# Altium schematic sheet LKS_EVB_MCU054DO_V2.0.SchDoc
size A4; SheetNumber: 1; SheetTotal: 1
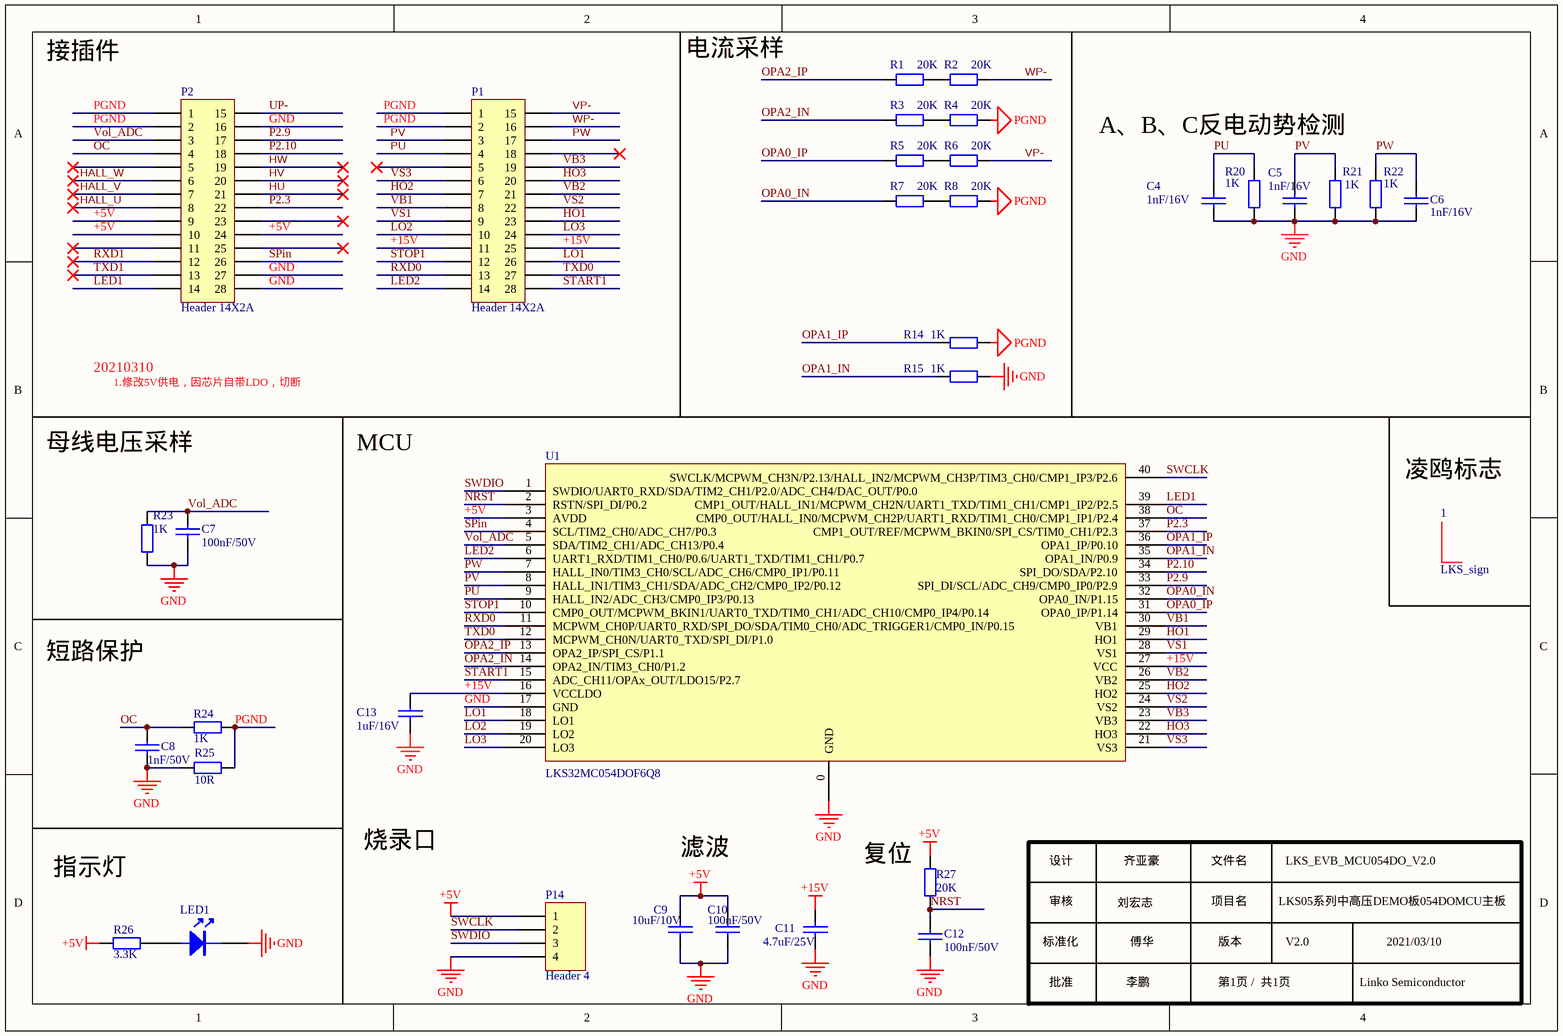
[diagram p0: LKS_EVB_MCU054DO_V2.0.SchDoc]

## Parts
1  LKS_sign  [LKS_LOGO2]
C4  1nF/16V  [0603C]
C5  1nF/16V  [0603C]
C6  1nF/16V  [0603C]
C7  100nF/50V  [0603C]
C8  1nF/50V  [0603C]
C9  10uF/10V  [0603C]
C10  100nF/50V  [0603C]
C11  4.7uF/25V  [0603C]
C12  100nF/50V  [0603C]
C13  1uF/16V  [0603C]
LED1  LED  [LED 0603R]  (value not drawn)
P1  Header 14X2A  [HDR2X14_CEN]
P2  Header 14X2A  [HDR2X14_CEN]
P14  Header 4  [HDR1X4]
R1  20K  [0603R]
R2  20K  [0603R]
R3  20K  [0603R]
R4  20K  [0603R]
R5  20K  [0603R]
R6  20K  [0603R]
R7  20K  [0603R]
R8  20K  [0603R]
R14  1K  [0603R]
R15  1K  [0603R]
R20  1K  [0603R]
R21  1K  [0603R]
R22  1K  [0603R]
R23  1K  [0603R]
R24  1K  [0603R]
R25  10R  [0603R]
R26  3.3K  [0603R]
R27  20K  [0603R]
U1  LKS32MC054DOF6Q8  [QFN40]

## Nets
+5V: C9.2 C10.2 P2.9 P2.10 P2.24 P14.1 R26.2 R27.1 U1.3(AVDD)
+15V: C11.2 C13.1 P1.11 P1.25 U1.16(VCCLDO) U1.27(VCC)
GND: C4.2 C5.2 C6.2 C7.1 C8.1 C9.1 C10.1 C11.1 C12.2 C13.2 LED1.2(K) P2.16 P2.27 P2.28 P14.4 R15.1 R20.2 R21.2 R22.2 R23.1 R25.2 U1.0(GND) U1.17(GND)
PGND: P1.1 P1.2 P2.1 P2.2 R4.1 R8.1 R14.1 R24.2 R25.1
HALL_U: P2.8
HALL_V: P2.7
HALL_W: P2.6
HO1: P1.23 U1.29(HO1)
HO2: P1.7 U1.25(HO2)
HO3: P1.20 U1.22(HO3)
HU: P2.21
HV: P2.20
HW: P2.19
LED1: P2.14 U1.39(CMP1_OUT/HALL_IN1/MCPWM_CH2N/UART1_TXD/TIM1_CH1/CMP1_IP2/P2.5)
LED2: P1.14 U1.6(UART1_RXD/TIM1_CH0/P0.6/UART1_TXD/TIM1_CH1/P0.7)
LO1: P1.26 U1.18(LO1)
LO2: P1.10 U1.19(LO2)
LO3: P1.24 U1.20(LO3)
NRST: C12.1 R27.2 U1.2(RSTN/SPI_DI/P0.2)
OC: C8.2 P2.4 R24.1 U1.38(CMP0_OUT/HALL_IN0/MCPWM_CH2P/UART1_RXD/TIM1_CH0/CMP1_IP1/P2.4)
OPA0_IN: R7.2 U1.32(OPA0_IN/P1.15)
OPA0_IP: R5.2 U1.31(OPA0_IP/P1.14)
OPA1_IN: R15.2 U1.35(OPA1_IN/P0.9)
OPA1_IP: R14.2 U1.36(OPA1_IP/P0.10)
OPA2_IN: R3.2 U1.14(OPA2_IN/TIM3_CH0/P1.2)
OPA2_IP: R1.2 U1.13(OPA2_IP/SPI_CS/P1.1)
P2.3: P2.22 U1.37(CMP1_OUT/REF/MCPWM_BKIN0/SPI_CS/TIM0_CH1/P2.3)
P2.9: P2.17 U1.33(SPI_DI/SCL/ADC_CH9/CMP0_IP0/P2.9)
P2.10: P2.18 U1.34(SPI_DO/SDA/P2.10)
PU: C4.1 P1.4 R20.1 U1.9(HALL_IN2/ADC_CH3/CMP0_IP3/P0.13)
PV: C5.1 P1.3 R21.1 U1.8(HALL_IN1/TIM3_CH1/SDA/ADC_CH2/CMP0_IP2/P0.12)
PW: C6.1 P1.17 R22.1 U1.7(HALL_IN0/TIM3_CH0/SCL/ADC_CH6/CMP0_IP1/P0.11)
RXD0: P1.13 U1.11(MCPWM_CH0P/UART0_RXD/SPI_DO/SDA/TIM0_CH0/ADC_TRIGGER1/CMP0_IN/P0.15)
RXD1: P2.12
SPin: P2.26 U1.4(SCL/TIM2_CH0/ADC_CH7/P0.3)
START1: P1.28 U1.15(ADC_CH11/OPAx_OUT/LDO15/P2.7)
STOP1: P1.12 U1.10(CMP0_OUT/MCPWM_BKIN1/UART0_TXD/TIM0_CH1/ADC_CH10/CMP0_IP4/P0.14)
SWCLK: P14.2 U1.40(SWCLK/MCPWM_CH3N/P2.13/HALL_IN2/MCPWM_CH3P/TIM3_CH0/CMP1_IP3/P2.6)
SWDIO: P14.3 U1.1(SWDIO/UART0_RXD/SDA/TIM2_CH1/P2.0/ADC_CH4/DAC_OUT/P0.0)
TXD0: P1.27 U1.12(MCPWM_CH0N/UART0_TXD/SPI_DI/P1.0)
TXD1: P2.13
UP-: P2.15
VB1: P1.8 U1.30(VB1)
VB2: P1.21 U1.26(VB2)
VB3: P1.19 U1.23(VB3)
Vol_ADC: C7.2 P2.3 R23.2 U1.5(SDA/TIM2_CH1/ADC_CH13/P0.4)
VP-: P1.15 R6.1
VS1: P1.9 U1.28(VS1)
VS2: P1.22 U1.24(VS2)
VS3: P1.6 U1.21(VS3)
WP-: P1.16 R2.1
NetLED1_1: LED1.1(A) R26.1
NetR1_1: R1.1 R2.2
NetR3_1: R3.1 R4.2
NetR5_1: R5.1 R6.2
NetR7_1: R7.1 R8.2

Not connected (* = marked no-connect by the designer): P1 5* 18*; P2 5* 11* 23* 25*

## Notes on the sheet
- 接插件
- 20210310
- 1.修改5V供电，因芯片自带LDO，切断
- 母线电压采样
- (near 1) 凌鸥标志
- 短路保护
- 烧录口
- 指示灯
- 滤波
- (near R27) 复位
- 设计
- 审核
- 刘宏志
- 齐亚豪
- 文件名
- 项目名
- LKS05系列中高压DEMO板054DOMCU主板
- LKS_EVB_MCU054DO_V2.0
- 标准化
- 批准
- 李鹏
- 傅华
- 版本
- 第1页 /  共1页
- V2.0
- Linko Semiconductor
- 2021/03/10
- Labels drawn without touching a wire or pin: A、B、C反电动势检测, MCU, 电流采样

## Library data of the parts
C4-C6 C13 = CAP: Capacitor
C7-C12 = C: Capacitor
LED1 = LED: LED_Light
P1 P2 = Header 14X2A: Header, 14-Pin, Dual row
P14 = Header 4: Header, 4-Pin
R1-R8 R14 R15 R20-R25 R27 = Res: Resistor; Value: K
R26 = Res: Resistor; Value: 330
U1 = LKS32MC054DOF6Q8: 芯片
